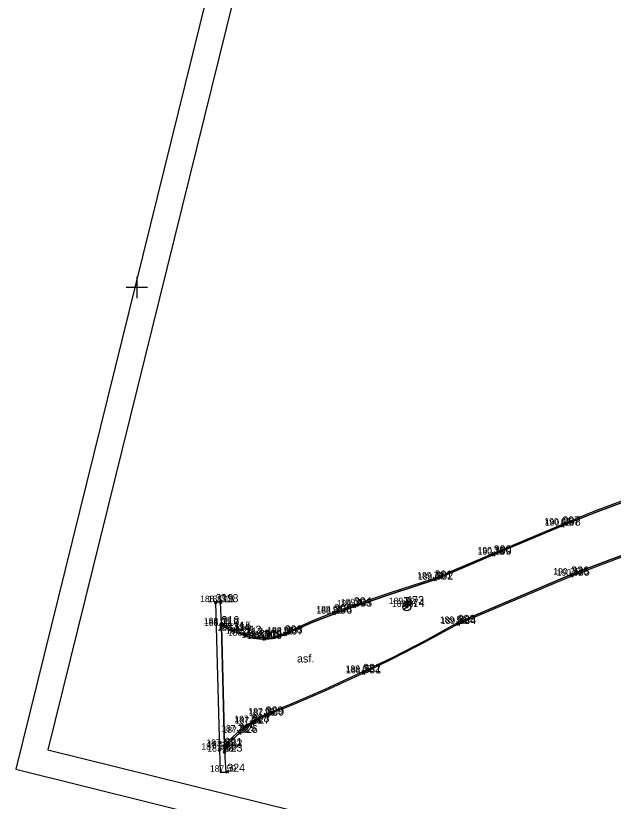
# Model space of a CAD drawing. Extents: x -706861 to -706379, y -1036456 to -1036201.
# Drawn here: x -706861.4 to -706805.3, y -1036348.1 to -1036274.5 of the extents above; entities that cross this region are included whole.
import ezdxf

# ---------------------------------------------------------------- set-up
doc = ezdxf.new("R2010")
doc.units = 0
for name, color, linetype in [('18_popisy', 7, 'Continuous'), ('29_vodovod', 7, 'Continuous'), ('40_plochy', 7, 'Continuous'), ('51_body polohopisu_značky', 7, 'Continuous'), ('52_body polohopisu_čísla', 7, 'Continuous'), ('53_body polohopisu_výšky', 7, 'Continuous'), ('54_body polohopisu_čísla nadbytečné pro kreslení', 7, 'Continuous'), ('5_rozhraní ploch', 7, 'Continuous'), ('60_mapový rám_legenda', 7, 'Continuous')]:
    doc.layers.add(name, color=color, linetype=linetype)

msp = doc.modelspace()

# ---------------------------------------------------------------- linework, layer by layer
at = {"layer": '29_vodovod'}
for p, q in [((-706824.994, -1036330.141), (-706824.404, -1036329.678)), ((-706824.95, -1036329.035), (-706824.45, -1036329.035)), ((-706824.7, -1036329.535), (-706824.7, -1036329.035))]:
    msp.add_line(p, q, dxfattribs=at)
for centre, radius in [((-706824.7, -1036329.91), 0.375), ((-706824.76, -1036329.65), 0.25)]:
    msp.add_circle(centre, radius, dxfattribs=at)
at = {"layer": '40_plochy'}
msp.add_lwpolyline([(-706801.54, -1036324.01), (-706805.43, -1036325.41), (-706809.29, -1036326.88), (-706819.93, -1036331.41), (-706822.99, -1036333.08), (-706826.08, -1036334.67), (-706829.21, -1036336.19), (-706832.37, -1036337.64), (-706835.57, -1036339.02), (-706837.94, -1036339.99), (-706838.82, -1036340.45), (-706839.66, -1036340.98), (-706840.47, -1036341.59), (-706841.19, -1036342.26), (-706841.8, -1036342.93), (-706842.06, -1036331.69), (-706840.97, -1036332.18), (-706839.85, -1036332.61), (-706839.2, -1036332.8), (-706838.57, -1036332.9), (-706837.93, -1036332.92), (-706837.3, -1036332.86), (-706836.68, -1036332.72), (-706836.08, -1036332.5), (-706835.49, -1036332.22), (-706833.51, -1036331.35), (-706831.49, -1036330.55), (-706830.15, -1036330.07), (-706826.1, -1036328.68), (-706822.02, -1036327.36), (-706816.54, -1036325.02), (-706810.07, -1036322.3), (-706806.94, -1036321.03), (-706804.25, -1036320.03)], dxfattribs=at)
at = {"layer": '51_body polohopisu_značky'}
for points in [[(-706810.24, -1036322.31), (-706810, -1036322.07)], [(-706810.24, -1036322.07), (-706810, -1036322.31)], [(-706810.19, -1036322.42), (-706809.95, -1036322.18)], [(-706810.19, -1036322.18), (-706809.95, -1036322.42)], [(-706816.68, -1036325.02), (-706816.44, -1036324.78)], [(-706816.68, -1036324.78), (-706816.44, -1036325.02)], [(-706816.66, -1036325.14), (-706816.42, -1036324.9)], [(-706816.66, -1036324.9), (-706816.42, -1036325.14)], [(-706809.41, -1036327), (-706809.17, -1036326.76)], [(-706809.41, -1036326.76), (-706809.17, -1036327)], [(-706822.22, -1036327.37), (-706821.98, -1036327.13)], [(-706822.22, -1036327.13), (-706821.98, -1036327.37)], [(-706822.14, -1036327.48), (-706821.9, -1036327.24)], [(-706822.14, -1036327.24), (-706821.9, -1036327.48)], [(-706809.34, -1036327.11), (-706809.1, -1036326.87)], [(-706809.34, -1036326.87), (-706809.1, -1036327.11)], [(-706842.74, -1036329.58), (-706842.5, -1036329.34)], [(-706842.74, -1036329.34), (-706842.5, -1036329.58)], [(-706842.27, -1036329.59), (-706842.03, -1036329.35)], [(-706842.27, -1036329.35), (-706842.03, -1036329.59)], [(-706829.79, -1036329.88), (-706829.55, -1036329.64)], [(-706829.79, -1036329.64), (-706829.55, -1036329.88)], [(-706824.88, -1036329.77), (-706824.64, -1036329.53)], [(-706824.88, -1036329.53), (-706824.64, -1036329.77)], [(-706831.65, -1036330.54), (-706831.41, -1036330.3)], [(-706831.65, -1036330.3), (-706831.41, -1036330.54)], [(-706831.61, -1036330.67), (-706831.37, -1036330.43)], [(-706831.61, -1036330.43), (-706831.37, -1036330.67)], [(-706829.73, -1036330), (-706829.49, -1036329.76)], [(-706829.73, -1036329.76), (-706829.49, -1036330)], [(-706824.82, -1036330.03), (-706824.58, -1036329.79)], [(-706824.82, -1036329.79), (-706824.58, -1036330.03)], [(-706842.2, -1036331.65), (-706841.96, -1036331.41)], [(-706842.2, -1036331.41), (-706841.96, -1036331.65)], [(-706842.18, -1036331.81), (-706841.94, -1036331.57)], [(-706842.18, -1036331.57), (-706841.94, -1036331.81)], [(-706841.06, -1036332.16), (-706840.82, -1036331.92)], [(-706841.06, -1036331.92), (-706840.82, -1036332.16)], [(-706820.05, -1036331.53), (-706819.81, -1036331.29)], [(-706820.05, -1036331.29), (-706819.81, -1036331.53)], [(-706819.98, -1036331.63), (-706819.74, -1036331.39)], [(-706819.98, -1036331.39), (-706819.74, -1036331.63)], [(-706841.13, -1036332.29), (-706840.89, -1036332.05)], [(-706841.13, -1036332.05), (-706840.89, -1036332.29)], [(-706840.12, -1036332.54), (-706839.88, -1036332.3)], [(-706840.12, -1036332.3), (-706839.88, -1036332.54)], [(-706839.97, -1036332.73), (-706839.73, -1036332.49)], [(-706839.97, -1036332.49), (-706839.73, -1036332.73)], [(-706836.26, -1036332.51), (-706836.02, -1036332.27)], [(-706836.26, -1036332.27), (-706836.02, -1036332.51)], [(-706836.2, -1036332.62), (-706835.96, -1036332.38)], [(-706836.2, -1036332.38), (-706835.96, -1036332.62)], [(-706838.7, -1036332.91), (-706838.46, -1036332.67)], [(-706838.7, -1036332.67), (-706838.46, -1036332.91)], [(-706838.2, -1036332.93), (-706837.96, -1036332.69)], [(-706838.2, -1036332.69), (-706837.96, -1036332.93)], [(-706838.18, -1036333.04), (-706837.94, -1036332.8)], [(-706838.18, -1036332.8), (-706837.94, -1036333.04)], [(-706828.92, -1036336.12), (-706828.68, -1036335.88)], [(-706828.92, -1036335.88), (-706828.68, -1036336.12)], [(-706828.89, -1036336.24), (-706828.65, -1036336)], [(-706828.89, -1036336), (-706828.65, -1036336.24)], [(-706838.06, -1036340.11), (-706837.82, -1036339.87)], [(-706838.06, -1036339.87), (-706837.82, -1036340.11)], [(-706838, -1036340.22), (-706837.76, -1036339.98)], [(-706838, -1036339.98), (-706837.76, -1036340.22)], [(-706839.37, -1036340.83), (-706839.13, -1036340.59)], [(-706839.37, -1036340.59), (-706839.13, -1036340.83)], [(-706839.31, -1036340.96), (-706839.07, -1036340.72)], [(-706839.31, -1036340.72), (-706839.07, -1036340.96)], [(-706840.6, -1036341.71), (-706840.36, -1036341.47)], [(-706840.6, -1036341.47), (-706840.36, -1036341.71)], [(-706840.47, -1036341.84), (-706840.23, -1036341.6)], [(-706840.47, -1036341.6), (-706840.23, -1036341.84)], [(-706841.92, -1036343.05), (-706841.68, -1036342.81)], [(-706841.92, -1036342.81), (-706841.68, -1036343.05)], [(-706841.9, -1036343.2), (-706841.66, -1036342.96)], [(-706841.9, -1036342.96), (-706841.66, -1036343.2)], [(-706842.39, -1036343.41), (-706842.15, -1036343.17)], [(-706842.39, -1036343.17), (-706842.15, -1036343.41)], [(-706841.9, -1036343.59), (-706841.66, -1036343.35)], [(-706841.9, -1036343.35), (-706841.66, -1036343.59)], [(-706841.65, -1036345.47), (-706841.41, -1036345.23)], [(-706841.65, -1036345.23), (-706841.41, -1036345.47)]]:
    msp.add_lwpolyline(points, dxfattribs=at)
at = {"layer": '5_rozhraní ploch'}
for points in [[(-706798.85, -1036318.14), (-706801.6, -1036318.99), (-706804.32, -1036319.92), (-706807.01, -1036320.93), (-706809.68, -1036322.01), (-706810.11, -1036322.19)], [(-706798.79, -1036318.26), (-706801.53, -1036319.11), (-706804.25, -1036320.03), (-706806.94, -1036321.03), (-706809.6, -1036322.1), (-706810.07, -1036322.3)], [(-706810.11, -1036322.19), (-706816.56, -1036324.9), (-706822.1, -1036327.25)], [(-706810.07, -1036322.3), (-706816.54, -1036325.02), (-706822.02, -1036327.36)], [(-706809.29, -1036326.88), (-706805.43, -1036325.41), (-706801.54, -1036324.01), (-706797.63, -1036322.69), (-706797.04, -1036322.5)], [(-706809.22, -1036326.99), (-706804.95, -1036325.39), (-706800.66, -1036323.86), (-706796.99, -1036322.62)], [(-706822.02, -1036327.36), (-706826.1, -1036328.68), (-706830.15, -1036330.07), (-706831.49, -1036330.55)], [(-706822.1, -1036327.25), (-706826.26, -1036328.59), (-706829.67, -1036329.76)], [(-706819.93, -1036331.41), (-706809.29, -1036326.88)], [(-706819.86, -1036331.51), (-706809.22, -1036326.99)], [(-706842.08, -1036331.53), (-706842.15, -1036329.47), (-706842.62, -1036329.46), (-706842.27, -1036343.29), (-706842.18, -1036345.41)], [(-706829.67, -1036329.76), (-706831.66, -1036330.47), (-706833.61, -1036331.25), (-706835.54, -1036332.11), (-706836.14, -1036332.39)], [(-706831.49, -1036330.55), (-706833.51, -1036331.35), (-706835.49, -1036332.22), (-706836.08, -1036332.5)], [(-706842.08, -1036331.53), (-706842.06, -1036331.69), (-706841.8, -1036342.93), (-706841.78, -1036343.08), (-706841.78, -1036343.47), (-706841.67, -1036345.41), (-706842.18, -1036345.41)], [(-706838.57, -1036332.79), (-706839.42, -1036332.6), (-706840.25, -1036332.33), (-706840.94, -1036332.04), (-706842.08, -1036331.53)], [(-706839.85, -1036332.61), (-706840.97, -1036332.18), (-706842.06, -1036331.69)], [(-706819.93, -1036331.41), (-706822.99, -1036333.08), (-706826.08, -1036334.67), (-706829.21, -1036336.19), (-706832.37, -1036337.64), (-706835.57, -1036339.02), (-706837.94, -1036339.99)], [(-706819.86, -1036331.51), (-706822.93, -1036333.18), (-706826.03, -1036334.78), (-706829.17, -1036336.31), (-706832.34, -1036337.76), (-706835.54, -1036339.15), (-706837.88, -1036340.1)], [(-706836.08, -1036332.5), (-706836.68, -1036332.72), (-706837.3, -1036332.86), (-706837.93, -1036332.92), (-706838.57, -1036332.9), (-706839.2, -1036332.8), (-706839.85, -1036332.61)], [(-706836.14, -1036332.39), (-706836.73, -1036332.61), (-706837.34, -1036332.75), (-706837.96, -1036332.81), (-706838.57, -1036332.79)], [(-706837.94, -1036339.99), (-706838.82, -1036340.45), (-706839.66, -1036340.98), (-706840.47, -1036341.59)], [(-706837.88, -1036340.1), (-706838.71, -1036340.54), (-706839.5, -1036341.05), (-706840.24, -1036341.62), (-706840.35, -1036341.72)], [(-706841.8, -1036342.93), (-706841.19, -1036342.26), (-706840.47, -1036341.59)], [(-706841.78, -1036343.08), (-706841, -1036342.29), (-706840.35, -1036341.72)]]:
    msp.add_lwpolyline(points, dxfattribs=at)
at = {"layer": '60_mapový rám_legenda'}
for p, q in [((-706825.716, -1036200.962), (-706861.359, -1036345.121)), ((-706823.89, -1036203.989), (-706858.332, -1036343.294)), ((-706858.332, -1036343.294), (-706416.71, -1036452.483)), ((-706861.359, -1036345.121), (-706414.883, -1036455.51))]:
    msp.add_line(p, q, dxfattribs=at)
for points in [[(-706850, -1036299), (-706850, -1036300), (-706850, -1036301)], [(-706849, -1036300), (-706850, -1036300), (-706851, -1036300)]]:
    msp.add_lwpolyline(points, dxfattribs=at)

# ---------------------------------------------------------------- texts
at = {"layer": '18_popisy'}
msp.add_text('asf.', height=0.75, dxfattribs=at).set_placement((-706834.99, -1036335.12))
at = {"layer": '52_body polohopisu_čísla'}
for s, p in [('297', (-706810.12, -1036322.19)), ('300', (-706816.56, -1036324.9)), ('301', (-706822.1, -1036327.25)), ('335', (-706809.22, -1036326.99)), ('318', (-706842.15, -1036329.47)), ('473', (-706824.76, -1036329.65)), ('305', (-706831.53, -1036330.42)), ('303', (-706829.61, -1036329.88)), ('316', (-706842.08, -1036331.53)), ('334', (-706819.86, -1036331.51)), ('312', (-706840, -1036332.42)), ('307', (-706836.08, -1036332.5)), ('331', (-706828.77, -1036336.12)), ('329', (-706837.94, -1036339.99)), ('325', (-706840.48, -1036341.59)), ('320', (-706842.27, -1036343.29))]:
    msp.add_text(s, height=0.75, dxfattribs=at).set_placement(p)
at = {"layer": '53_body polohopisu_výšky'}
for s, p in [('190 67 ', (-706811.806, -1036322.19)), ('190 59 ', (-706811.745, -1036322.3)), ('190 18 ', (-706818.06, -1036324.9)), ('190 13 ', (-706818.04, -1036325.02)), ('189 73 ', (-706823.72, -1036327.25)), ('189 67 ', (-706823.657, -1036327.36)), ('190 35 ', (-706810.96, -1036326.88)), ('190 41 ', (-706810.649, -1036326.99)), ('188 12 ', (-706844.066, -1036329.46)), ('188 11 ', (-706843.355, -1036329.47)), ('189 04 ', (-706831.256, -1036329.88)), ('189 11 ', (-706830.879, -1036329.76)), ('189 32 ', (-706826.38, -1036329.65)), ('189 31 ', (-706826.079, -1036329.91)), ('188 96 ', (-706833.181, -1036330.42)), ('188 90 ', (-706833.16, -1036330.55)), ('188 03 ', (-706843.722, -1036331.53)), ('188 02 ', (-706843.702, -1036331.69)), ('189 50 ', (-706821.602, -1036331.41)), ('189 56 ', (-706821.513, -1036331.51)), ('188 13 ', (-706842.456, -1036332.17)), ('188 19 ', (-706842.39, -1036332.04)), ('188 26 ', (-706841.649, -1036332.42)), ('188 56 ', (-706837.789, -1036332.39)), ('188 50 ', (-706837.748, -1036332.5)), ('188 23 ', (-706841.466, -1036332.61)), ('188 37 ', (-706840.196, -1036332.79)), ('188 34 ', (-706839.676, -1036332.92)), ('188 41 ', (-706839.455, -1036332.81)), ('188 68 ', (-706830.432, -1036336)), ('188 74 ', (-706830.386, -1036336.12)), ('187 93 ', (-706839.558, -1036339.99)), ('187 99 ', (-706839.503, -1036340.1)), ('187 83 ', (-706840.866, -1036340.71)), ('187 88 ', (-706840.806, -1036340.84)), ('187 72 ', (-706842.096, -1036341.59)), ('187 78 ', (-706841.966, -1036341.72)), ('187 60 ', (-706843.954, -1036343.29)), ('187 60 ', (-706843.484, -1036342.93)), ('187 59 ', (-706843.4, -1036343.08)), ('187 58 ', (-706843.396, -1036343.47)), ('187 59 ', (-706843.15, -1036345.35))]:
    msp.add_text(s, height=0.6, dxfattribs=at).set_placement(p)
at = {"layer": '54_body polohopisu_čísla nadbytečné pro kreslení'}
for s, p in [('298', (-706810.07, -1036322.3)), ('299', (-706816.54, -1036325.02)), ('302', (-706822.02, -1036327.36)), ('336', (-706809.29, -1036326.88)), ('319', (-706842.62, -1036329.46)), ('304', (-706829.67, -1036329.76)), ('474', (-706824.7, -1036329.91)), ('306', (-706831.49, -1036330.55)), ('317', (-706842.06, -1036331.69)), ('333', (-706819.93, -1036331.41)), ('314', (-706841.01, -1036332.17)), ('315', (-706840.94, -1036332.04)), ('313', (-706839.85, -1036332.61)), ('308', (-706836.14, -1036332.39)), ('311', (-706838.58, -1036332.79)), ('309', (-706838.08, -1036332.81)), ('310', (-706838.06, -1036332.92)), ('332', (-706828.8, -1036336)), ('328', (-706839.25, -1036340.71)), ('330', (-706837.88, -1036340.1)), ('327', (-706839.19, -1036340.84)), ('326', (-706840.35, -1036341.72)), ('321', (-706841.8, -1036342.93)), ('322', (-706841.78, -1036343.08)), ('323', (-706841.78, -1036343.47)), ('324', (-706841.53, -1036345.35))]:
    msp.add_text(s, height=0.75, dxfattribs=at).set_placement(p)

doc.saveas('drawing.dxf')
